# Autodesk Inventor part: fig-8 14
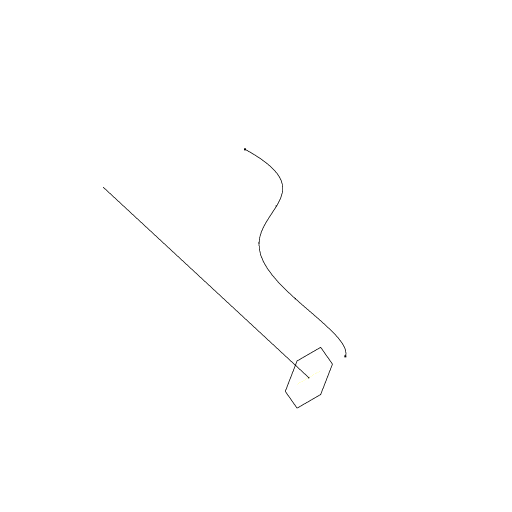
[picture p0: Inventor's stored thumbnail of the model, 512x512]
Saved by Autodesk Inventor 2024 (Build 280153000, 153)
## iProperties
Created: 2004-05
Part Number: fig-8 14
Document SubType Name: Modeling
Designer: CADCIM Technologies
Manufacturer: Standard
Standards Organization: Custom
Density: 1 g/cm^3
Material: Generic
Appearance: Default
Author: CADCIM Technologies
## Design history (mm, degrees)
workplane "Work Plane2"
sketch "Sketch7"
  geometry: L1 (-42.583, 6.068)-(-42.583, 0.37) reference; 5 further points
  constraints: 1 point on line, 5 other
sketch "Sketch8"
  geometry: L1 (-42.583, 3.219)-(-107.269, 18.236); L2 (-42.583, 6.068)-(-42.583, 0.37) reference
  constraints: 2 end point, 1 midpoint
sketch "Sketch2"
  geometry: L1 (-5.697, 0)-(-2.849, 4.934); L2 (-2.849, 4.934)-(2.849, 4.934); L3 (2.849, 4.934)-(5.697, 0); L4 (5.697, 0)-(2.849, -4.934); L5 (2.849, -4.934)-(-2.849, -4.934); L6 (-2.849, -4.934)-(-5.697, 0); 2 further points
  constraints: 12 end point, 1 coincident, 12 other
